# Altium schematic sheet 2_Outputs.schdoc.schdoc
size 309 x 223 mm; Symbol: Sheet-Symbol_A4; Device: Sheet-Symbol_A4; Company: Velizy Astro Club; Drawed: Paul V.; Reviewed: Denis G.; Version: V1.1; Page Size: A4; @Project Name: AstrAlim; @Page Count: 2; @Update Date: 2024-03-29; @Create Date: 2024-02-04; @Schematic Name: AstrAlim SCH; Part Number: AstrAlim-v1.1; @Page No: 2; @Page Name: Outputs.AstrAlim SCH
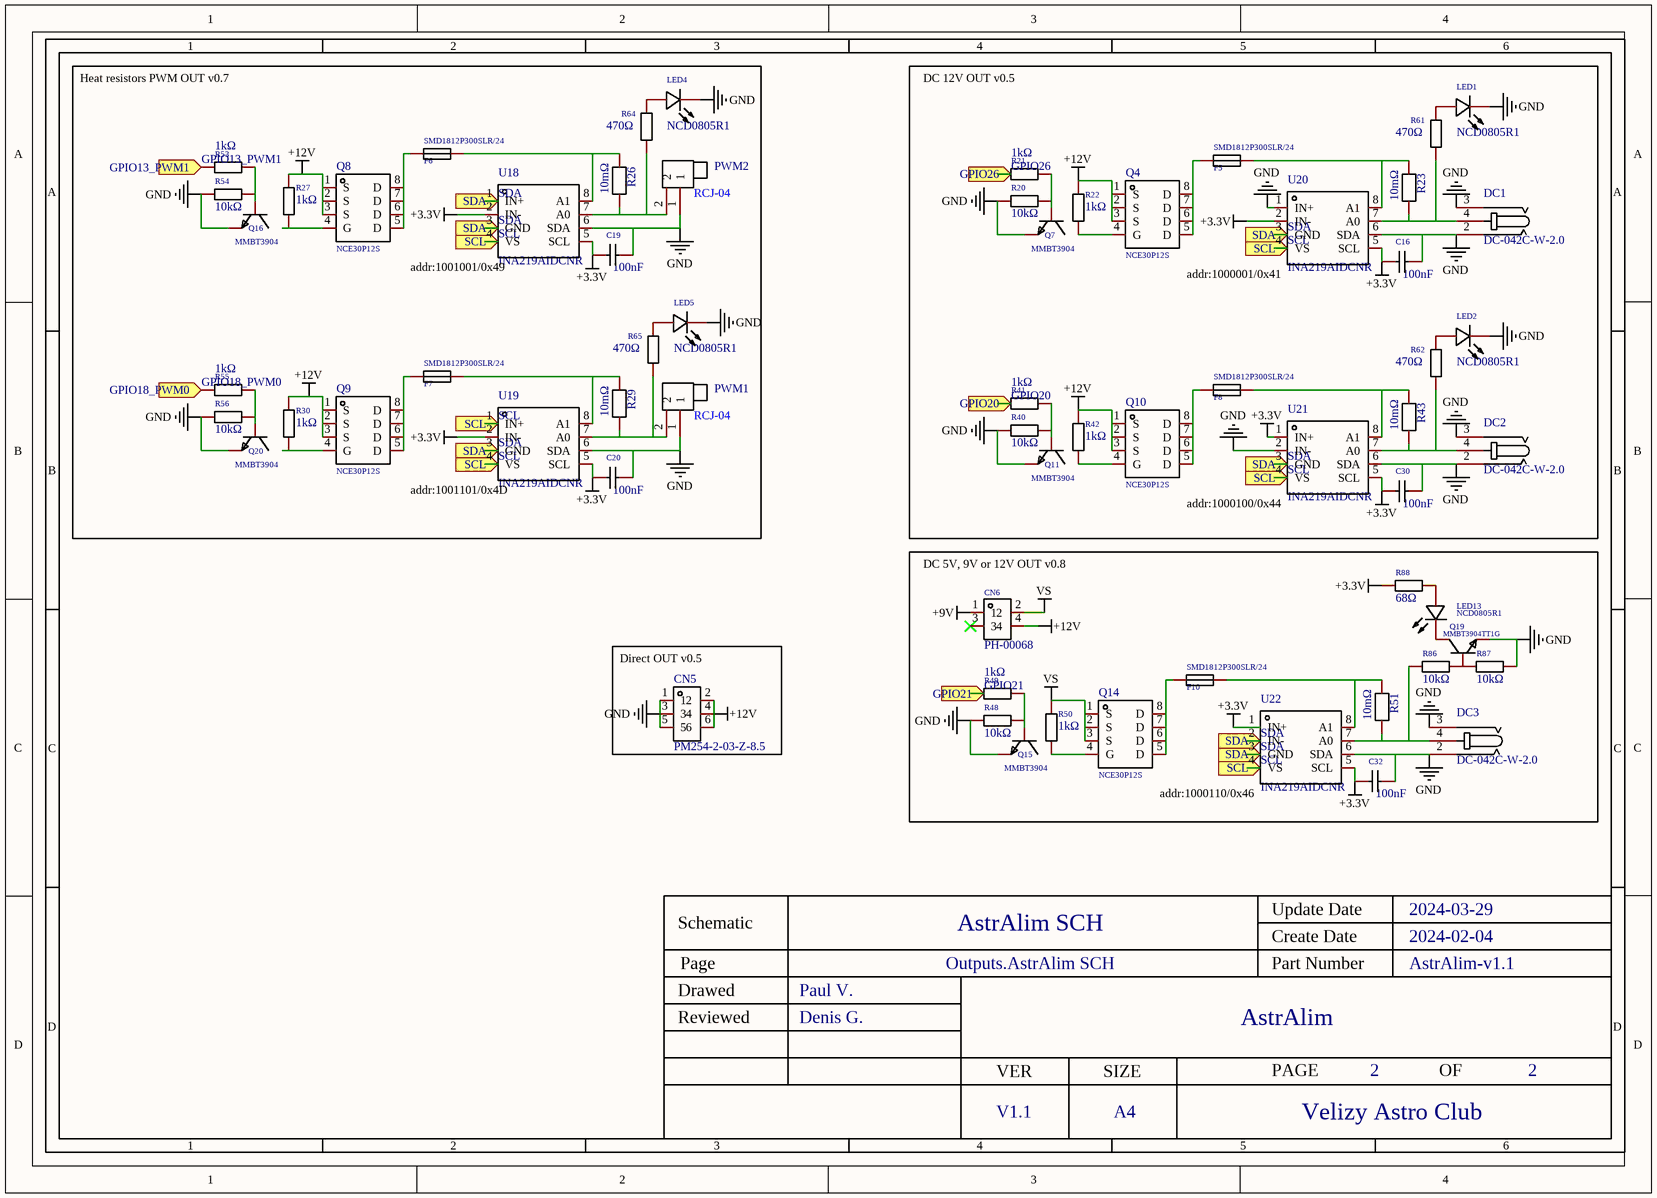
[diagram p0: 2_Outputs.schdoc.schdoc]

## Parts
C16  100nF  [C0402]
C19  100nF  [C0402]
C20  100nF  [C0402]
C30  100nF  [C0402]
C32  100nF  [C0402]
CN5  PM254-2-03-Z-8.5  [HDR-TH_6P-P2.54-V-F-R2-C3-S2.54]
CN6  PH-00068  [HDR-TH_4P-P2.54-V-M-R2-C2-S2.54]
DC1  DC-042C-W-2.0  [DC-IN-TH_DC-042C-W-2.0]
DC2  DC-042C-W-2.0  [DC-IN-TH_DC-042C-W-2.0]
DC3  DC-042C-W-2.0  [DC-IN-TH_DC-042C-W-2.0]
F5  SMD1812P300SLR/24  [F1812]
F6  SMD1812P300SLR/24  [F1812]
F7  SMD1812P300SLR/24  [F1812]
F8  SMD1812P300SLR/24  [F1812]
F10  SMD1812P300SLR/24  [F1812]
LED1  NCD0805R1  [LED0805-R-RD]
LED2  NCD0805R1  [LED0805-R-RD]
LED4  NCD0805R1  [LED0805-R-RD]
LED5  NCD0805R1  [LED0805-R-RD]
LED13  NCD0805R1  [LED0805-R-RD]
PWM1  AV-5  [RCJ-04]  (value not drawn)
PWM2  AV-5  [RCJ-04]  (value not drawn)
Q4  NCE30P12S  [SOIC-8_L4.9-W3.9-P1.27-LS6.0-BL]
Q7  MMBT3904  [SOT-23-3_L2.9-W1.3-P1.90-LS2.4-BR]
Q8  NCE30P12S  [SOIC-8_L4.9-W3.9-P1.27-LS6.0-BL]
Q9  NCE30P12S  [SOIC-8_L4.9-W3.9-P1.27-LS6.0-BL]
Q10  NCE30P12S  [SOIC-8_L4.9-W3.9-P1.27-LS6.0-BL]
Q11  MMBT3904  [SOT-23-3_L2.9-W1.3-P1.90-LS2.4-BR]
Q14  NCE30P12S  [SOIC-8_L4.9-W3.9-P1.27-LS6.0-BL]
Q15  MMBT3904  [SOT-23-3_L2.9-W1.3-P1.90-LS2.4-BR]
Q16  MMBT3904  [SOT-23-3_L2.9-W1.3-P1.90-LS2.4-BR]
Q19  MMBT3904TT1G  [SC-75-3_L1.6-W0.8-P1.00-LS1.6-BR]
Q20  MMBT3904  [SOT-23-3_L2.9-W1.3-P1.90-LS2.4-BR]
R20  10kΩ  [R0402]
R21  1kΩ  [R0402]
R22  1kΩ  [R0402]
R23  10mΩ  [R1206]
R26  10mΩ  [R1206]
R27  1kΩ  [R0402]
R29  10mΩ  [R1206]
R30  1kΩ  [R0402]
R40  10kΩ  [R0402]
R41  1kΩ  [R0402]
R42  1kΩ  [R0402]
R43  10mΩ  [R1206]
R48  10kΩ  [R0402]
R49  1kΩ  [R0402]
R50  1kΩ  [R0402]
R51  10mΩ  [R1206]
R53  1kΩ  [R0402]
R54  10kΩ  [R0402]
R55  1kΩ  [R0402]
R56  10kΩ  [R0402]
R61  470Ω  [R0402]
R62  470Ω  [R0402]
R64  470Ω  [R0402]
R65  470Ω  [R0402]
R86  10kΩ  [R0402]
R87  10kΩ  [R0402]
R88  68Ω  [R0603]
U18  INA219AIDCNR  [SOT-23-8_L3.0-W1.7-P0.65-LS2.8-BR]
U19  INA219AIDCNR  [SOT-23-8_L3.0-W1.7-P0.65-LS2.8-BR]
U20  INA219AIDCNR  [SOT-23-8_L3.0-W1.7-P0.65-LS2.8-BR]
U21  INA219AIDCNR  [SOT-23-8_L3.0-W1.7-P0.65-LS2.8-BR]
U22  INA219AIDCNR  [SOT-23-8_L3.0-W1.7-P0.65-LS2.8-BR]

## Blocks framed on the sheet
Direct OUT v0.5: CN5

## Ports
GPIO13_PWM1 (in), GPIO18_PWM0 (in), GPIO20 (in), GPIO21 (in), GPIO26 (in), SCL (in), SDA (in)

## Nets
+3.3V: C16.1 C19.1 C20.1 C30.1 C32.1 R88.1 U18.2(IN-) U18.5(SCL) U19.2(IN-) U19.5(SCL) U20.2(IN-) U20.5(SCL) U21.1(IN+) U21.5(SCL) U22.1(IN+) U22.5(SCL)
+9V: CN6.1
+12V: CN5.2 CN5.4 CN5.6 CN6.4 Q4.1(S) Q4.2(S) Q4.3(S) Q8.1(S) Q8.2(S) Q8.3(S) Q9.1(S) Q9.2(S) Q9.3(S) Q10.1(S) Q10.2(S) Q10.3(S) R22.2 R27.2 R30.2 R42.2
GND: C16.2 C19.2 C20.2 C30.2 C32.2 CN5.1 CN5.3 CN5.5 DC1.2 DC1.3 DC2.2 DC2.3 DC3.2 DC3.3 LED1.2(-) LED2.2(-) LED4.2(-) LED5.2(-) PWM1.1 PWM2.1 Q7.2(E) Q11.2(E) Q15.2(E) Q16.2(E) Q19.2(E) Q20.2(E) R20.1 R40.1 R48.1 R54.1 R56.1 R87.1 U18.6(SDA) U19.6(SDA) U20.1(IN+) U20.6(SDA) U21.2(IN-) U21.6(SDA) U22.6(SDA)
VS: CN6.2 Q14.1(S) Q14.2(S) Q14.3(S) R50.2
GPIO13_PWM1: R53.1 ; port GPIO13_PWM1
GPIO18_PWM0: R55.1 ; port GPIO18_PWM0
GPIO20: R41.1 ; port GPIO20
GPIO21: R49.1 ; port GPIO21
GPIO26: R21.1 ; port GPIO26
SCL: U18.4(VS) U19.1(IN+) U19.4(VS) U20.4(VS) U21.4(VS) U22.4(VS) ; port SCL
SDA: U18.1(IN+) U18.3(GND) U19.3(GND) U20.3(GND) U21.3(GND) U22.2(IN-) U22.3(GND) ; port SDA
NetDC1_4: DC1.4 R23.1 R61.1 U20.7(A0)
NetDC2_4: DC2.4 R43.1 R62.1 U21.7(A0)
NetDC3_4: DC3.4 R51.1 R86.2 U22.7(A0)
NetF5_1: F5.1 R23.2 U20.8(A1)
NetF5_2: F5.2 Q4.5(D) Q4.6(D) Q4.7(D) Q4.8(D)
NetF6_1: F6.1 R26.2 U18.8(A1)
NetF6_2: F6.2 Q8.5(D) Q8.6(D) Q8.7(D) Q8.8(D)
NetF7_1: F7.1 R29.2 U19.8(A1)
NetF7_2: F7.2 Q9.5(D) Q9.6(D) Q9.7(D) Q9.8(D)
NetF8_1: F8.1 R43.2 U21.8(A1)
NetF8_2: F8.2 Q10.5(D) Q10.6(D) Q10.7(D) Q10.8(D)
NetF10_1: F10.1 R51.2 U22.8(A1)
NetF10_2: F10.2 Q14.5(D) Q14.6(D) Q14.7(D) Q14.8(D)
NetLED1_1: LED1.1(+) R61.2
NetLED2_1: LED2.1(+) R62.2
NetLED4_1: LED4.1(+) R64.2
NetLED5_1: LED5.1(+) R65.2
NetLED13_1: LED13.1(+) R88.2
NetLED13_2: LED13.2(-) Q19.3(C)
NetPWM1_2: PWM1.2 R29.1 R65.1 U19.7(A0)
NetPWM2_2: PWM2.2 R26.1 R64.1 U18.7(A0)
NetQ4_4: Q4.4(G) R22.1
NetQ7_1: Q7.1(B) R20.2 R21.2
NetQ8_4: Q8.4(G) R27.1
NetQ9_4: Q9.4(G) R30.1
NetQ10_4: Q10.4(G) R42.1
NetQ11_1: Q11.1(B) R40.2 R41.2
NetQ14_4: Q14.4(G) R50.1
NetQ15_1: Q15.1(B) R48.2 R49.2
NetQ16_1: Q16.1(B) R53.2 R54.2
NetQ19_1: Q19.1(B) R86.1 R87.2
NetQ20_1: Q20.1(B) R55.2 R56.2

Not connected (* = marked no-connect by the designer): CN6 3*; Q7 3(C); Q11 3(C); Q15 3(C); Q16 3(C); Q20 3(C)

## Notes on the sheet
- Heat resistors PWM OUT v0.7
- DC 12V OUT v0.5
- (near PWM2) RCJ-04
- (near U18) addr:1001001/0x49
- addr:1000001/0x41
- (near PWM1) RCJ-04
- (near U19) addr:1001101/0x4D
- addr:1000100/0x44
- (near CN6) DC 5V, 9V or 12V OUT v0.8
- addr:1000110/0x46

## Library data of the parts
C16 C19 C20 C30 C32 = CL05B104KO5NNNC: Manufacturer: SAMSUNG(三星); Add into BOM: yes; Tolerance: ±10%; Description: Capacitance: Tolerance:±10% Tolerance:±10% Voltage Rated: Temperature Coefficient:
CN5 = PM254-2-03-Z-8.5: Manufacturer: HCTL(华灿天禄); Add into BOM: no; Convert to PCB: yes; Holes Structure: 2x3P; Pitch: 2.54mm; Circular Hole / Square Hole: Square Holes; Number of Holes: 6P; Current Rating (Max): 3A; Holes Direction: Top; Soldering Temperature(Max): 260℃@5S; Description: Holes Structure:2x3P Pitch:2.54mm Row Spacing:2.54mm Circular Hole / Square Hole:Square Holes Mounting Type:Straight Number of Rows:双排 Number of Holes:6P Current Rating (Max):3A Voltage Rating (Max):- Holes Direction:Top Insulation Height:8.5mm Contact Ma
CN6 = PH-00068: Manufacturer: Liansheng(连盛); Add into BOM: no; Convert to PCB: yes; Pin Structure: 2x2P; Pitch: 2.54mm; Circluar Pins/Square Pins: Square Pins; Current Rating (Max): 3A; Description: Pin Structure:2x2P Pitch:2.54mm Number of Pins:4P Mounting Type:Straight Number of Rows:双排 Row Spacing:2.54mm Circluar Pins/Square Pins:Square Pins Current Rating (Max):3A Voltage Rating (Max):- Length of Mating Pin:6mm Insulation Height:2.5mm Length of E
DC1-DC3 = DC-042C-W-2.0: Manufacturer: XKB Connectivity(中国星坤); Add into BOM: yes; Connector Type: DC Power Receptacle; Inside Contact Diameter: 2mm; Outside Contact Diameter: 6.3mm; Current Rating (Max): 8A; Voltage Rating (Max): 24V; Welding Temperature (Max): 260℃; Description: Connector Type:DC Power Receptacle Inside Contact Diameter:2mm Outside Contact Diameter:6.3mm Current Rating (Max):8A Voltage Rating (Max):24V Contact Material:Brass Operating Temperature Range:-20℃~+70℃ Operating Temperature Range:-20℃~+70℃ Welding Tempe
F5-F8 F10 = SMD1812P300SLR/24_C2892380: Manufacturer: PTTC(聚鼎); Add into BOM: yes; Operating Voltage (Max): 24V; Current Rating (Max): 50A; Hold Current: 3A; Trip Current: 6A; Power Dissipation: 2W; Resistance - Initial (Ri) (Min): 0.001Ω; Resistance - Post Trip (R1) (Max): 0.03Ω; Maximum Time to Trip: 2s; Description: Operating Voltage (Max):24V Current Rating (Max):50A Hold Current:3A Trip Current:6A Power Dissipation:2W Resistance - Initial (Ri) (Min):0.001Ω Resistance - Post Trip (R1) (Max):0.03Ω Maximum Time to Trip:2s Operating Temperature:-40℃~+85℃ Operating Temp
LED1 LED2 LED4 LED5 LED13 = NCD0805R1_C84256: Manufacturer: 国星光电; Symbol: FC-2012HRK-620D; Add into BOM: yes; Emitted Color: Red; Forward Voltage (VF): 1.6V~2.6V; Forward Current: 20mA; Power Dissipation: 65mW; Lens Color: 无色透明; Dominant Wavelength: 615nm~630nm; Luminous Intensity: 67mcd~195mcd; Viewing Angle: 130°; Description: Emitted Color:Red Diode Configuration:- Lamp Holder Type:- Forward Voltage (VF):1.6V~2.6V Forward Voltage (VF):1.6V~2.6V Forward Current:20mA Power Dissipation:65mW Lens Color:无色透明 Dominant Wavelength:615nm~630nm Dominant Wavelength:615nm~630nm Peak Wavel
PWM1 PWM2 = AV-5: Manufacturer: BOOMELE(博穆精密); Add into BOM: no; Convert to PCB: yes; Connector Type: 3.5mm耳机座; Description: Connector Type:3.5mm耳机座 Current Rating (Max):- Voltage Rating (Max):- Operating Temperature Range:- Operating Temperature Range:-
Q4 Q8-Q10 Q14 = NCE30P12S: Manufacturer: NCE(无锡新洁能); Add into BOM: yes; Drain Source On Resistance (RDS(on)@Vgs,Id): 15mΩ@10V,10A; Gate Threshold Voltage (Vgs(th)@Id): 3V@250uA; Description: Type: Drain Source Voltage (Vdss): Continuous Drain Current (Id): Power Dissipation (Pd): Drain Source On Resistance (RDS(on)@Vgs,Id):15mΩ@10V,10A Gate Threshold Voltage (Vgs(th)@Id):3V@250uA
Q7 Q11 Q15 Q16 Q20 = MMBT3904_C20526: Manufacturer: CJ(江苏长电/长晶); Add into BOM: yes; DC Current Gain (hFE@Ic,Vce): 100@10mA,1V; Transition Frequency (fT): 300MHz; Collector Cut-Off Current (Icbo): 100nA; Collector-Emitter Saturation Voltage (VCE(sat)@Ic,Ib): 300mV@50mA,5mA; Description: Transistor Type: Collector Current (Ic): Collector-Emitter Breakdown Voltage (Vceo): Power Dissipation (Pd): DC Current Gain (hFE@Ic,Vce):100@10mA,1V DC Current Gain (hFE@Ic,Vce):100@10mA,1V Transition Frequency (fT):300MHz Collector Cut-Off Current (Icbo
Q19 = MMBT3904TT1G: Manufacturer: onsemi(安森美); Add into BOM: yes; DC Current Gain (hFE@Ic,Vce): 100@10mA,1V; Transition Frequency (fT): 300MHz; Collector-Emitter Saturation Voltage (VCE(sat)@Ic,Ib): 300mV@5mA,50mA; Description: Transistor Type: Collector Current (Ic): Collector-Emitter Breakdown Voltage (Vceo): Power Dissipation (Pd): DC Current Gain (hFE@Ic,Vce):100@10mA,1V DC Current Gain (hFE@Ic,Vce):100@10mA,1V Transition Frequency (fT):300MHz Collector-Emitter Saturation Vo
R20 R40 R48 R54 R56 R86 R87 = 0402WGF1002TCE: Manufacturer: UNI-ROYAL(厚声); Add into BOM: yes; Tolerance: ±1%; Temperature Coefficient: ±100ppm/℃; Description: Resistance:10000Ω Tolerance:±1% Tolerance:±1% Power(Watts): Overload Voltage (Max): Temperature Coefficient:±100ppm/℃ Temperature Coefficient:±100ppm/℃ Type:Thick Film Resistors Operating Temperature Range:-55℃~+155℃ Operating Temperature Range:-55℃~+155℃
R21 R22 R27 R30 R41 R42 R49 R50 R53 R55 = 0402WGF1001TCE: Manufacturer: UNI-ROYAL(厚声); Add into BOM: yes; Tolerance: ±1%; Temperature Coefficient: ±100ppm/℃; Description: Resistance:1000Ω Tolerance:±1% Tolerance:±1% Power(Watts): Overload Voltage (Max): Temperature Coefficient:±100ppm/℃ Temperature Coefficient:±100ppm/℃ Type:Thick Film Resistors Operating Temperature Range:-55℃~+155℃ Operating Temperature Range:-55℃~+155℃
R23 R26 R29 R43 R51 = MFJ06HR010FT: Manufacturer: FH(风华); Add into BOM: yes; Tolerance: ±1%; Temperature Coefficient: ±50ppm/℃; Description: Resistance:10mΩ Tolerance:±1% Tolerance:±1% Power(Watts): Temperature Coefficient:±50ppm/℃ Temperature Coefficient:±50ppm/℃ Overload Voltage (Max):- Operating Temperature Range:-55℃~+170℃ Operating Temperature Range:-55℃~+170℃
R61 R62 R64 R65 = 0402WGF4700TCE: Manufacturer: UNI-ROYAL(厚声); Add into BOM: yes; Tolerance: ±1%; Temperature Coefficient: ±100ppm/℃; Description: Resistance: Tolerance:±1% Tolerance:±1% Power(Watts): Overload Voltage (Max): Temperature Coefficient:±100ppm/℃ Temperature Coefficient:±100ppm/℃ Type:Thick Film Resistors Operating Temperature Range:-55℃~+155℃ Operating Temperature Range:-55℃~+155℃
R88 = 0603WAF680JT5E: Manufacturer: UNI-ROYAL(厚声); Add into BOM: yes; Tolerance: ±1%; Temperature Coefficient: ±100ppm/℃; Description: Resistance:68000mΩ Tolerance:±1% Tolerance:±1% Power(Watts): Overload Voltage (Max): Temperature Coefficient:±100ppm/℃ Temperature Coefficient:±100ppm/℃ Type:Thick Film Resistors Operating Temperature Range:-55℃~+155℃ Operating Temperature Range:-55℃~+155
U18-U22 = INA219AIDCNR: Manufacturer: TI(德州仪器); Add into BOM: yes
